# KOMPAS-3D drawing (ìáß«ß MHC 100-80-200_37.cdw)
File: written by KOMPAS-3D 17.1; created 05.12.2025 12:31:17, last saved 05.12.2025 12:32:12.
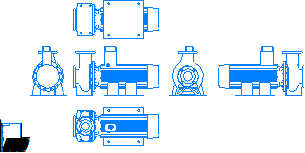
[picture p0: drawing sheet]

Sheet 1: A4, portrait

Title block, sheet 1: name: Насос MHC 100-80-200_30 / 30,0 кВт 3х380В; material: Сталь 10  ГОСТ 1050-88; mass: 310,89; sheets: 1; sheet format: A4

Views: Проекционный вид 2, Проекционный вид 3, Проекционный вид 4, Проекционный вид 5, Проекционный вид 6
Referenced files in \\adlc.lan\data\АДЛ_ПКД\3D-модели\ADL production\Насосы ГРАНПАМП\Насосы ГРАНПАМП серии МНС\KOMPAS 3D\: Насос MHC 100-80-200_37.m3d
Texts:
  Andrey
  АДЛ
Dimensions and other numbers on the sheet: 1:1; 1; 30,0 кВт 3х380В; 310,89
